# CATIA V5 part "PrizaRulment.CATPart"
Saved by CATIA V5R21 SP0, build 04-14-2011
Part number: PrizaRulment
Bounding box of the stored display mesh (mm): x -12 to 12, y -11.818 to 11.818, z 76 to 84
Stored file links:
  C:\Users\MIRCEA\Desktop\PRRO\CATIAV5\PrizaRulment.CATPart
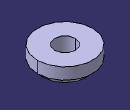
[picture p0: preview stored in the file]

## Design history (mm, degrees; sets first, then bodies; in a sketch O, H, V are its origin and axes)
Body1 (main body)
  Plane1: type Offset, RefPlane xy-plane, Offset 84
  Sketch1 on Plane1, origin (0, 0, 84), H (1, 0, 0), V (0, 1, 0)
    circle A1 centre (0, 0) radius 4.5
    circle A2 centre (0, 0) radius 12
    radius A1 = 4.5
    radius A2 = 12
  Pad1: profile Sketch1, direction (0, 0, -1), length 8
  Chamfer1: length 3, angle 45, on edge [end face of Pad1 | face of Pad1 from Sketch1.A2]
